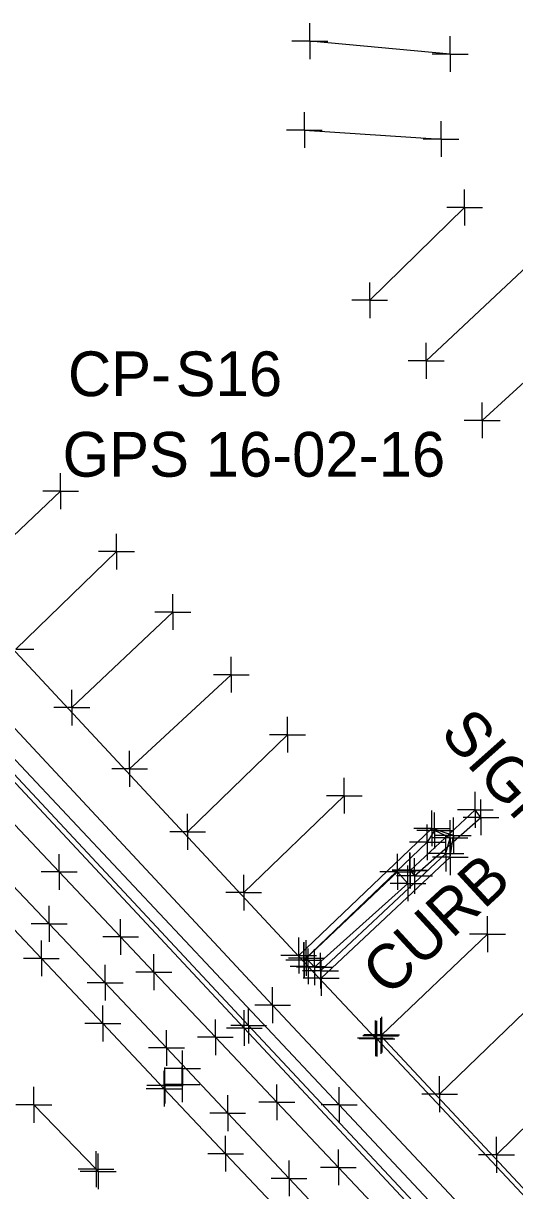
# Model space of a CAD drawing. Extents: x 0 to 1944463, y 0 to 420651.
# Drawn here: x 1943479.5 to 1943534.4, y 417193.2 to 417323.7 of the extents above; entities that cross this region are included whole.
import ezdxf

# ---------------------------------------------------------------- set-up
doc = ezdxf.new("R2010")
doc.units = 0
for name, color, linetype in [('SUR - CTRL - Points - Numbers', 7, 'Continuous'), ('SUR - CTRL - Points Text', 7, 'Continuous'), ('SUR - DTM - Breaklines', 7, 'Continuous'), ('SUR - DTM - Breaklines - Points - Locators', 7, 'Continuous'), ('SUR - NON-TRAN - Features', 7, 'Continuous'), ('SUR - NON-TRAN - Features - Points - Locators', 7, 'Continuous'), ('SUR - NON-TRAN - Features Text', 7, 'Continuous'), ('SUR - PROPERTY - Property Lines', 7, 'Continuous'), ('SUR - TR-CTRL - Pavement Marking', 7, 'Continuous'), ('SUR - TR-CTRL - Pavement Marking - Points - Locators', 7, 'Continuous'), ('SUR - TRAN - Features', 7, 'Continuous'), ('SUR - TRAN - Features - Points - Locators', 7, 'Continuous'), ('SUR - TRAN - Features Text', 7, 'Continuous'), ('SUR - TRAN - Roads', 7, 'Continuous'), ('SUR - TRAN - Roadside Barriers', 7, 'Continuous'), ('SUR - TRAN - Roadside Barriers - Points - Locators', 7, 'Continuous'), ('SUR - UTL - Water', 7, 'Continuous'), ('SUR - UTL - Water - Points - Locators', 7, 'Continuous')]:
    doc.layers.add(name, color=color, linetype=linetype)

msp = doc.modelspace()

# ---------------------------------------------------------------- linework, layer by layer
at = {"layer": 'SUR - DTM - Breaklines'}
for points in [[(1943599.21, 417115.36), (1943596.21, 417115.03), (1943594.9, 417115.36), (1943561.47, 417150.87), (1943532.76, 417181.59), (1943504.67, 417211.66), (1943469.66, 417249.17), (1943442.44, 417278.51), (1943441.49, 417280.1), (1943441.55, 417281.81), (1943442.66, 417283.41)], [(1943512.69, 417217.8), (1943526.69, 417230.89), (1943527.17, 417232.63), (1943525.44, 417233.46), (1943524.63, 417232.15), (1943510.82, 417218.96)], [(1943623.39, 417132.78), (1943623.9, 417130.37), (1943623.49, 417128.38), (1943622.43, 417126.54), (1943611.92, 417116.71), (1943608.74, 417116.12), (1943606.85, 417116.84), (1943570.39, 417155.84), (1943540.03, 417188.46), (1943519.42, 417210.51)]]:
    msp.add_lwpolyline(points, dxfattribs=at)
at = {"layer": 'SUR - DTM - Breaklines - Points - Locators'}
for p, q in [((1943525.44, 417233.46), (1943525.44, 417235.46)), ((1943524.63, 417232.15), (1943524.63, 417234.15)), ((1943527.17, 417232.63), (1943527.17, 417234.63)), ((1943525.44, 417233.46), (1943523.44, 417233.46)), ((1943525.44, 417233.46), (1943527.44, 417233.46)), ((1943525.44, 417233.46), (1943525.44, 417231.46)), ((1943526.69, 417230.89), (1943526.69, 417232.89)), ((1943524.63, 417232.15), (1943522.63, 417232.15)), ((1943524.63, 417232.15), (1943526.63, 417232.15)), ((1943524.63, 417232.15), (1943524.63, 417230.15)), ((1943527.17, 417232.63), (1943525.17, 417232.63)), ((1943527.17, 417232.63), (1943529.17, 417232.63)), ((1943527.17, 417232.63), (1943527.17, 417230.63)), ((1943526.69, 417230.89), (1943524.69, 417230.89)), ((1943526.69, 417230.89), (1943528.69, 417230.89)), ((1943526.69, 417230.89), (1943526.69, 417228.89)), ((1943510.82, 417218.96), (1943510.82, 417220.96)), ((1943512.69, 417217.8), (1943512.69, 417219.8)), ((1943510.82, 417218.96), (1943508.82, 417218.96)), ((1943510.82, 417218.96), (1943512.82, 417218.96)), ((1943510.82, 417218.96), (1943510.82, 417216.96)), ((1943512.69, 417217.8), (1943510.69, 417217.8)), ((1943512.69, 417217.8), (1943514.69, 417217.8)), ((1943512.69, 417217.8), (1943512.69, 417215.8)), ((1943504.67, 417211.66), (1943504.67, 417213.66)), ((1943519.42, 417210.51), (1943519.42, 417212.51)), ((1943504.67, 417211.66), (1943502.67, 417211.66)), ((1943504.67, 417211.66), (1943506.67, 417211.66)), ((1943504.67, 417211.66), (1943504.67, 417209.66)), ((1943519.42, 417210.51), (1943517.42, 417210.51)), ((1943519.42, 417210.51), (1943521.42, 417210.51)), ((1943519.42, 417210.51), (1943519.42, 417208.51))]:
    msp.add_line(p, q, dxfattribs=at)
at = {"layer": 'SUR - NON-TRAN - Features'}
for points in [[(1943522.69, 417229.02), (1943523.2, 417228.39), (1943530.62, 417234.93), (1943529.99, 417235.78), (1943522.7, 417228.98)], [(1943511.11, 417219.21), (1943512.03, 417218.19), (1943522.47, 417227.56), (1943521.31, 417228.85), (1943510.86, 417218.97)]]:
    msp.add_lwpolyline(points, dxfattribs=at)
at = {"layer": 'SUR - NON-TRAN - Features - Points - Locators'}
for p, q in [((1943529.99, 417235.78), (1943529.99, 417237.78)), ((1943530.62, 417234.93), (1943530.62, 417236.93)), ((1943529.99, 417235.78), (1943527.99, 417235.78)), ((1943529.99, 417235.78), (1943531.99, 417235.78)), ((1943529.99, 417235.78), (1943529.99, 417233.78)), ((1943530.62, 417234.93), (1943528.62, 417234.93)), ((1943530.62, 417234.93), (1943532.62, 417234.93)), ((1943530.62, 417234.93), (1943530.62, 417232.93)), ((1943521.31, 417228.85), (1943521.31, 417230.85)), ((1943522.69, 417229.02), (1943522.69, 417231.02)), ((1943522.7, 417228.98), (1943522.7, 417230.98)), ((1943523.2, 417228.39), (1943523.2, 417230.39)), ((1943521.31, 417228.85), (1943519.31, 417228.85)), ((1943522.69, 417229.02), (1943520.69, 417229.02)), ((1943522.7, 417228.98), (1943520.7, 417228.98)), ((1943521.31, 417228.85), (1943523.31, 417228.85)), ((1943521.31, 417228.85), (1943521.31, 417226.85)), ((1943522.47, 417227.56), (1943522.47, 417229.56)), ((1943522.69, 417229.02), (1943524.69, 417229.02)), ((1943522.69, 417229.02), (1943522.69, 417227.02)), ((1943522.7, 417228.98), (1943524.7, 417228.98)), ((1943522.7, 417228.98), (1943522.7, 417226.98)), ((1943522.47, 417227.56), (1943520.47, 417227.56)), ((1943523.2, 417228.39), (1943521.2, 417228.39)), ((1943522.47, 417227.56), (1943524.47, 417227.56)), ((1943522.47, 417227.56), (1943522.47, 417225.56)), ((1943523.2, 417228.39), (1943525.2, 417228.39)), ((1943523.2, 417228.39), (1943523.2, 417226.39)), ((1943511.11, 417219.21), (1943511.11, 417221.21)), ((1943510.86, 417218.97), (1943510.86, 417220.97)), ((1943512.03, 417218.19), (1943512.03, 417220.19)), ((1943510.86, 417218.97), (1943508.86, 417218.97)), ((1943511.11, 417219.21), (1943509.11, 417219.21)), ((1943510.86, 417218.97), (1943512.86, 417218.97)), ((1943510.86, 417218.97), (1943510.86, 417216.97)), ((1943511.11, 417219.21), (1943513.11, 417219.21)), ((1943511.11, 417219.21), (1943511.11, 417217.21)), ((1943512.03, 417218.19), (1943510.03, 417218.19)), ((1943512.03, 417218.19), (1943514.03, 417218.19)), ((1943512.03, 417218.19), (1943512.03, 417216.19))]:
    msp.add_line(p, q, dxfattribs=at)
at = {"layer": 'SUR - PROPERTY - Property Lines'}
for p, q in [((1943483.51, 417228.84), (1943483.51, 417230.84)), ((1943483.51, 417228.84), (1943481.51, 417228.84)), ((1943483.51, 417228.84), (1943485.51, 417228.84)), ((1943483.51, 417228.84), (1943483.51, 417226.84)), ((1943490.37, 417221.57), (1943490.37, 417223.57)), ((1943490.37, 417221.57), (1943488.37, 417221.57)), ((1943490.37, 417221.57), (1943492.37, 417221.57)), ((1943490.37, 417221.57), (1943490.37, 417219.57)), ((1943494.09, 417217.63), (1943494.09, 417219.63)), ((1943494.09, 417217.63), (1943492.09, 417217.63)), ((1943494.09, 417217.63), (1943496.09, 417217.63)), ((1943494.09, 417217.63), (1943494.09, 417215.63)), ((1943500.96, 417210.36), (1943500.96, 417212.36)), ((1943500.96, 417210.36), (1943498.96, 417210.36)), ((1943500.96, 417210.36), (1943502.96, 417210.36)), ((1943500.96, 417210.36), (1943500.96, 417208.36)), ((1943507.82, 417203.09), (1943507.82, 417205.09)), ((1943507.82, 417203.09), (1943505.82, 417203.09)), ((1943507.82, 417203.09), (1943509.82, 417203.09)), ((1943507.82, 417203.09), (1943507.82, 417201.09)), ((1943514.69, 417195.82), (1943514.69, 417197.82)), ((1943514.69, 417195.82), (1943512.69, 417195.82)), ((1943514.69, 417195.82), (1943516.69, 417195.82)), ((1943514.69, 417195.82), (1943514.69, 417193.82))]:
    msp.add_line(p, q, dxfattribs=at)
at = {"layer": 'SUR - TR-CTRL - Pavement Marking'}
for points in [[(1943527.18, 417320.25), (1943511.5, 417321.68)], [(1943510.9, 417311.75), (1943526.16, 417310.75)], [(1943528.8, 417303.1), (1943518.19, 417292.73)], [(1943524.5, 417285.96), (1943536.4, 417297.12)], [(1943408.36, 417296.41), (1943415.25, 417289.16), (1943422.15, 417281.92), (1943429.05, 417274.68), (1943435.95, 417267.44), (1943440.35, 417262.82), (1943447.21, 417255.54), (1943454.07, 417248.27), (1943460.93, 417240.99), (1943467.79, 417233.72), (1943474.66, 417226.44), (1943481.52, 417219.17), (1943488.38, 417211.89), (1943495.24, 417204.61), (1943502.1, 417197.34), (1943507.91, 417191.17)], [(1943542.83, 417290.31), (1943530.76, 417279.3)], [(1943483.67, 417271.39), (1943472.3, 417260.63)], [(1943478.68, 417253.73), (1943489.91, 417264.64)], [(1943496.2, 417257.88), (1943484.93, 417247.2)], [(1943491.38, 417240.36), (1943502.73, 417250.88)], [(1943509.02, 417244.17), (1943497.86, 417233.32)], [(1943504.12, 417226.53), (1943515.35, 417237.35)], [(1943519.53, 417210.64), (1943531.35, 417221.88)], [(1943537.65, 417215.25), (1943526, 417204)], [(1943532.36, 417197.22), (1943543.85, 417208.51)], [(1943495.3, 417204.97), (1943497.23, 417205.09), (1943497.29, 417206.88)], [(1943480.68, 417202.8), (1943487.63, 417195.62), (1943487.87, 417195.37)]]:
    msp.add_lwpolyline(points, dxfattribs=at)
at = {"layer": 'SUR - TR-CTRL - Pavement Marking - Points - Locators'}
for p, q in [((1943511.5, 417321.68), (1943511.5, 417323.68)), ((1943511.5, 417321.68), (1943509.5, 417321.68)), ((1943511.5, 417321.68), (1943513.5, 417321.68)), ((1943511.5, 417321.68), (1943511.5, 417319.68)), ((1943527.18, 417320.25), (1943527.18, 417322.25)), ((1943527.18, 417320.25), (1943525.18, 417320.25)), ((1943527.18, 417320.25), (1943529.18, 417320.25)), ((1943527.18, 417320.25), (1943527.18, 417318.25)), ((1943510.9, 417311.75), (1943510.9, 417313.75)), ((1943526.16, 417310.75), (1943526.16, 417312.75)), ((1943510.9, 417311.75), (1943508.9, 417311.75)), ((1943510.9, 417311.75), (1943512.9, 417311.75)), ((1943510.9, 417311.75), (1943510.9, 417309.75)), ((1943526.16, 417310.75), (1943524.16, 417310.75)), ((1943526.16, 417310.75), (1943528.16, 417310.75)), ((1943526.16, 417310.75), (1943526.16, 417308.75)), ((1943528.8, 417303.1), (1943528.8, 417305.1)), ((1943528.8, 417303.1), (1943526.8, 417303.1)), ((1943528.8, 417303.1), (1943530.8, 417303.1)), ((1943528.8, 417303.1), (1943528.8, 417301.1)), ((1943518.19, 417292.73), (1943518.19, 417294.73)), ((1943518.19, 417292.73), (1943516.19, 417292.73)), ((1943518.19, 417292.73), (1943520.19, 417292.73)), ((1943518.19, 417292.73), (1943518.19, 417290.73)), ((1943524.5, 417285.96), (1943524.5, 417287.96)), ((1943524.5, 417285.96), (1943522.5, 417285.96)), ((1943524.5, 417285.96), (1943526.5, 417285.96)), ((1943524.5, 417285.96), (1943524.5, 417283.96)), ((1943530.76, 417279.3), (1943530.76, 417281.3)), ((1943530.76, 417279.3), (1943528.76, 417279.3)), ((1943530.76, 417279.3), (1943532.76, 417279.3)), ((1943530.76, 417279.3), (1943530.76, 417277.3)), ((1943483.67, 417271.39), (1943483.67, 417273.39)), ((1943483.67, 417271.39), (1943481.67, 417271.39)), ((1943483.67, 417271.39), (1943485.67, 417271.39)), ((1943483.67, 417271.39), (1943483.67, 417269.39)), ((1943489.91, 417264.64), (1943489.91, 417266.64)), ((1943489.91, 417264.64), (1943487.91, 417264.64)), ((1943489.91, 417264.64), (1943491.91, 417264.64)), ((1943489.91, 417264.64), (1943489.91, 417262.64)), ((1943496.2, 417257.88), (1943496.2, 417259.88)), ((1943496.2, 417257.88), (1943494.2, 417257.88)), ((1943496.2, 417257.88), (1943498.2, 417257.88)), ((1943496.2, 417257.88), (1943496.2, 417255.88)), ((1943478.68, 417253.73), (1943480.68, 417253.73)), ((1943502.73, 417250.88), (1943502.73, 417252.88)), ((1943502.73, 417250.88), (1943500.73, 417250.88)), ((1943502.73, 417250.88), (1943504.73, 417250.88)), ((1943502.73, 417250.88), (1943502.73, 417248.88)), ((1943484.93, 417247.2), (1943484.93, 417249.2)), ((1943484.93, 417247.2), (1943482.93, 417247.2)), ((1943484.93, 417247.2), (1943486.93, 417247.2)), ((1943484.93, 417247.2), (1943484.93, 417245.2)), ((1943509.02, 417244.17), (1943509.02, 417246.17)), ((1943509.02, 417244.17), (1943507.02, 417244.17)), ((1943509.02, 417244.17), (1943511.02, 417244.17)), ((1943509.02, 417244.17), (1943509.02, 417242.17)), ((1943491.38, 417240.36), (1943491.38, 417242.36)), ((1943491.38, 417240.36), (1943489.38, 417240.36)), ((1943491.38, 417240.36), (1943493.38, 417240.36)), ((1943491.38, 417240.36), (1943491.38, 417238.36)), ((1943515.35, 417237.35), (1943515.35, 417239.35)), ((1943515.35, 417237.35), (1943513.35, 417237.35)), ((1943515.35, 417237.35), (1943517.35, 417237.35)), ((1943515.35, 417237.35), (1943515.35, 417235.35)), ((1943497.86, 417233.32), (1943497.86, 417235.32)), ((1943497.86, 417233.32), (1943495.86, 417233.32)), ((1943497.86, 417233.32), (1943499.86, 417233.32)), ((1943497.86, 417233.32), (1943497.86, 417231.32)), ((1943504.12, 417226.53), (1943504.12, 417228.53)), ((1943504.12, 417226.53), (1943502.12, 417226.53)), ((1943504.12, 417226.53), (1943506.12, 417226.53)), ((1943504.12, 417226.53), (1943504.12, 417224.53)), ((1943531.35, 417221.88), (1943531.35, 417223.88)), ((1943481.52, 417219.17), (1943481.52, 417221.17)), ((1943531.35, 417221.88), (1943529.35, 417221.88)), ((1943531.35, 417221.88), (1943533.35, 417221.88)), ((1943531.35, 417221.88), (1943531.35, 417219.88)), ((1943481.52, 417219.17), (1943479.52, 417219.17)), ((1943481.52, 417219.17), (1943483.52, 417219.17)), ((1943481.52, 417219.17), (1943481.52, 417217.17)), ((1943488.38, 417211.89), (1943488.38, 417213.89)), ((1943488.38, 417211.89), (1943486.38, 417211.89)), ((1943488.38, 417211.89), (1943490.38, 417211.89)), ((1943488.38, 417211.89), (1943488.38, 417209.89)), ((1943519.53, 417210.64), (1943519.53, 417212.64)), ((1943519.53, 417210.64), (1943517.53, 417210.64)), ((1943519.53, 417210.64), (1943521.53, 417210.64)), ((1943519.53, 417210.64), (1943519.53, 417208.64)), ((1943497.29, 417206.88), (1943497.29, 417208.88)), ((1943497.29, 417206.88), (1943495.29, 417206.88)), ((1943495.3, 417204.97), (1943495.3, 417206.97)), ((1943497.23, 417205.09), (1943497.23, 417207.09)), ((1943497.29, 417206.88), (1943499.29, 417206.88)), ((1943497.29, 417206.88), (1943497.29, 417204.88)), ((1943495.24, 417204.61), (1943495.24, 417206.61)), ((1943526, 417204), (1943526, 417206)), ((1943480.68, 417202.8), (1943480.68, 417204.8)), ((1943495.24, 417204.61), (1943493.24, 417204.61)), ((1943495.3, 417204.97), (1943493.3, 417204.97)), ((1943497.23, 417205.09), (1943495.23, 417205.09)), ((1943495.24, 417204.61), (1943497.24, 417204.61)), ((1943495.24, 417204.61), (1943495.24, 417202.61)), ((1943495.3, 417204.97), (1943497.3, 417204.97)), ((1943495.3, 417204.97), (1943495.3, 417202.97)), ((1943497.23, 417205.09), (1943499.23, 417205.09)), ((1943497.23, 417205.09), (1943497.23, 417203.09)), ((1943480.68, 417202.8), (1943478.68, 417202.8)), ((1943480.68, 417202.8), (1943482.68, 417202.8)), ((1943480.68, 417202.8), (1943480.68, 417200.8)), ((1943526, 417204), (1943524, 417204)), ((1943526, 417204), (1943528, 417204)), ((1943526, 417204), (1943526, 417202)), ((1943502.1, 417197.34), (1943502.1, 417199.34)), ((1943532.36, 417197.22), (1943532.36, 417199.22)), ((1943487.63, 417195.62), (1943487.63, 417197.62)), ((1943487.87, 417195.37), (1943487.87, 417197.37)), ((1943502.1, 417197.34), (1943500.1, 417197.34)), ((1943502.1, 417197.34), (1943504.1, 417197.34)), ((1943502.1, 417197.34), (1943502.1, 417195.34)), ((1943532.36, 417197.22), (1943530.36, 417197.22)), ((1943532.36, 417197.22), (1943534.36, 417197.22)), ((1943532.36, 417197.22), (1943532.36, 417195.22)), ((1943487.63, 417195.62), (1943485.63, 417195.62)), ((1943487.87, 417195.37), (1943485.87, 417195.37)), ((1943487.63, 417195.62), (1943489.63, 417195.62)), ((1943487.63, 417195.62), (1943487.63, 417193.62)), ((1943487.87, 417195.37), (1943489.87, 417195.37)), ((1943487.87, 417195.37), (1943487.87, 417193.37))]:
    msp.add_line(p, q, dxfattribs=at)
at = {"layer": 'SUR - TRAN - Features'}
for points in [[(1943411.21, 417298.31), (1943418.1, 417291.06), (1943424.98, 417283.8), (1943431.86, 417276.55), (1943438.57, 417269.47), (1943445.42, 417262.19), (1943452.27, 417254.91), (1943459.12, 417247.62), (1943465.97, 417240.34), (1943468.61, 417237.53), (1943475.5, 417230.28), (1943482.39, 417223.03), (1943488.65, 417216.45), (1943495.49, 417209.16), (1943502.33, 417201.87), (1943509.18, 417194.58), (1943516.02, 417187.29)], [(1943518.83, 417210.24), (1943511.32, 417218.28), (1943477.13, 417255.04), (1943446.82, 417287.35)], [(1943599.45, 417114.82), (1943596.18, 417114.48), (1943594.76, 417114.82), (1943561.05, 417150.54), (1943532.29, 417181.29), (1943504.19, 417211.39), (1943469.29, 417248.73), (1943441.86, 417278.1), (1943440.95, 417279.86), (1943441.01, 417282.12), (1943441.75, 417283.37)], [(1943598.61, 417116.26), (1943564, 417153.26), (1943535.53, 417183.89), (1943507.35, 417213.95), (1943471.95, 417251.91), (1943442.68, 417283.56)], [(1943512.77, 417216.97), (1943527.19, 417230.47), (1943527.54, 417232.92), (1943525.14, 417233.7), (1943510.26, 417219.49)]]:
    msp.add_lwpolyline(points, dxfattribs=at)
at = {"layer": 'SUR - TRAN - Features - Points - Locators'}
for p, q in [((1943525.14, 417233.7), (1943525.14, 417235.7)), ((1943527.54, 417232.92), (1943527.54, 417234.92)), ((1943525.14, 417233.7), (1943523.14, 417233.7)), ((1943525.14, 417233.7), (1943527.14, 417233.7)), ((1943525.14, 417233.7), (1943525.14, 417231.7)), ((1943527.54, 417232.92), (1943525.54, 417232.92)), ((1943527.54, 417232.92), (1943529.54, 417232.92)), ((1943527.54, 417232.92), (1943527.54, 417230.92)), ((1943527.19, 417230.47), (1943527.19, 417232.47)), ((1943527.19, 417230.47), (1943525.19, 417230.47)), ((1943527.19, 417230.47), (1943529.19, 417230.47)), ((1943527.19, 417230.47), (1943527.19, 417228.47)), ((1943482.39, 417223.03), (1943482.39, 417225.03)), ((1943482.39, 417223.03), (1943480.39, 417223.03)), ((1943482.39, 417223.03), (1943484.39, 417223.03)), ((1943482.39, 417223.03), (1943482.39, 417221.03)), ((1943510.26, 417219.49), (1943510.26, 417221.49)), ((1943511.32, 417218.28), (1943511.32, 417220.28)), ((1943488.65, 417216.45), (1943488.65, 417218.45)), ((1943510.26, 417219.49), (1943508.26, 417219.49)), ((1943510.26, 417219.49), (1943512.26, 417219.49)), ((1943510.26, 417219.49), (1943510.26, 417217.49)), ((1943512.77, 417216.97), (1943512.77, 417218.97)), ((1943511.32, 417218.28), (1943509.32, 417218.28)), ((1943511.32, 417218.28), (1943513.32, 417218.28)), ((1943511.32, 417218.28), (1943511.32, 417216.28)), ((1943488.65, 417216.45), (1943486.65, 417216.45)), ((1943488.65, 417216.45), (1943490.65, 417216.45)), ((1943488.65, 417216.45), (1943488.65, 417214.45)), ((1943507.35, 417213.95), (1943507.35, 417215.95)), ((1943512.77, 417216.97), (1943510.77, 417216.97)), ((1943512.77, 417216.97), (1943514.77, 417216.97)), ((1943512.77, 417216.97), (1943512.77, 417214.97)), ((1943504.19, 417211.39), (1943504.19, 417213.39)), ((1943507.35, 417213.95), (1943505.35, 417213.95)), ((1943507.35, 417213.95), (1943509.35, 417213.95)), ((1943507.35, 417213.95), (1943507.35, 417211.95)), ((1943518.83, 417210.24), (1943518.83, 417212.24)), ((1943495.49, 417209.16), (1943495.49, 417211.16)), ((1943504.19, 417211.39), (1943502.19, 417211.39)), ((1943504.19, 417211.39), (1943506.19, 417211.39)), ((1943504.19, 417211.39), (1943504.19, 417209.39)), ((1943518.83, 417210.24), (1943516.83, 417210.24)), ((1943518.83, 417210.24), (1943520.83, 417210.24)), ((1943518.83, 417210.24), (1943518.83, 417208.24)), ((1943495.49, 417209.16), (1943493.49, 417209.16)), ((1943495.49, 417209.16), (1943497.49, 417209.16)), ((1943495.49, 417209.16), (1943495.49, 417207.16)), ((1943502.33, 417201.87), (1943502.33, 417203.87)), ((1943502.33, 417201.87), (1943500.33, 417201.87)), ((1943502.33, 417201.87), (1943504.33, 417201.87)), ((1943502.33, 417201.87), (1943502.33, 417199.87)), ((1943509.18, 417194.58), (1943509.18, 417196.58)), ((1943509.18, 417194.58), (1943507.18, 417194.58)), ((1943509.18, 417194.58), (1943511.18, 417194.58)), ((1943509.18, 417194.58), (1943509.18, 417192.58))]:
    msp.add_line(p, q, dxfattribs=at)
at = {"layer": 'SUR - TRAN - Roads'}
msp.add_lwpolyline([(1943407.52, 417315.29), (1943408.53, 417311.86), (1943409.96, 417308.76), (1943412.51, 417304.54), (1943415.94, 417300.45), (1943422.78, 417293.16), (1943424.91, 417290.89), (1943431.78, 417283.62), (1943438.65, 417276.35), (1943445.51, 417269.08), (1943452.38, 417261.81), (1943459.24, 417254.53), (1943462.91, 417250.65), (1943469.77, 417243.38), (1943476.64, 417236.11), (1943483.51, 417228.84), (1943490.37, 417221.57), (1943494.09, 417217.63), (1943500.96, 417210.36), (1943507.82, 417203.09), (1943514.69, 417195.82), (1943521.56, 417188.55)], dxfattribs=at)
at = {"layer": 'SUR - TRAN - Roadside Barriers'}
msp.add_lwpolyline([(1943624.18, 417133.16), (1943624.86, 417130.32), (1943624.35, 417128.09), (1943622.98, 417125.85), (1943612.49, 417116), (1943608.64, 417115.24), (1943606.17, 417116.23), (1943569.83, 417155.38), (1943539.61, 417188.15), (1943519, 417210.19)], dxfattribs=at)
at = {"layer": 'SUR - TRAN - Roadside Barriers - Points - Locators'}
for q in [(1943519, 417212.19), (1943517, 417210.19), (1943521, 417210.19), (1943519, 417208.19)]:
    msp.add_line((1943519, 417210.19), q, dxfattribs=at)
at = {"layer": 'SUR - UTL - Water'}
msp.add_lwpolyline([(1943736.14, 416965.92), (1943698.62, 417005.31), (1943662.81, 417044.53), (1943623.49, 417086.6), (1943587.47, 417125.24), (1943551.37, 417163.71), (1943514.78, 417202.79), (1943477.5, 417242.51), (1943442.36, 417279.47), (1943414.8, 417309.89), (1943402.76, 417322.35)], dxfattribs=at)
at = {"layer": 'SUR - UTL - Water - Points - Locators'}
for q in [(1943514.78, 417204.79), (1943512.78, 417202.79), (1943516.78, 417202.79), (1943514.78, 417200.79)]:
    msp.add_line((1943514.78, 417202.79), q, dxfattribs=at)

# ---------------------------------------------------------------- texts
at = {"layer": 'SUR - CTRL - Points - Numbers'}
for s, p in [('CP-', (1943484.49, 417282.01)), ('S16', (1943496.52, 417282.01))]:
    msp.add_text(s, height=5, dxfattribs=at).set_placement(p)
at = {"layer": 'SUR - CTRL - Points Text'}
msp.add_text('GPS 16-02-16', height=5, dxfattribs=at).set_placement((1943483.89, 417273.01))
at = {"layer": 'SUR - NON-TRAN - Features Text'}
msp.add_text('SIGN', height=5, rotation=311.6871, dxfattribs=at).set_placement((1943525.92, 417244.24))
at = {"layer": 'SUR - TRAN - Features Text'}
msp.add_text('CURB', height=5, rotation=42.6202, dxfattribs=at).set_placement((1943520.28, 417214.76))

doc.saveas('drawing.dxf')
